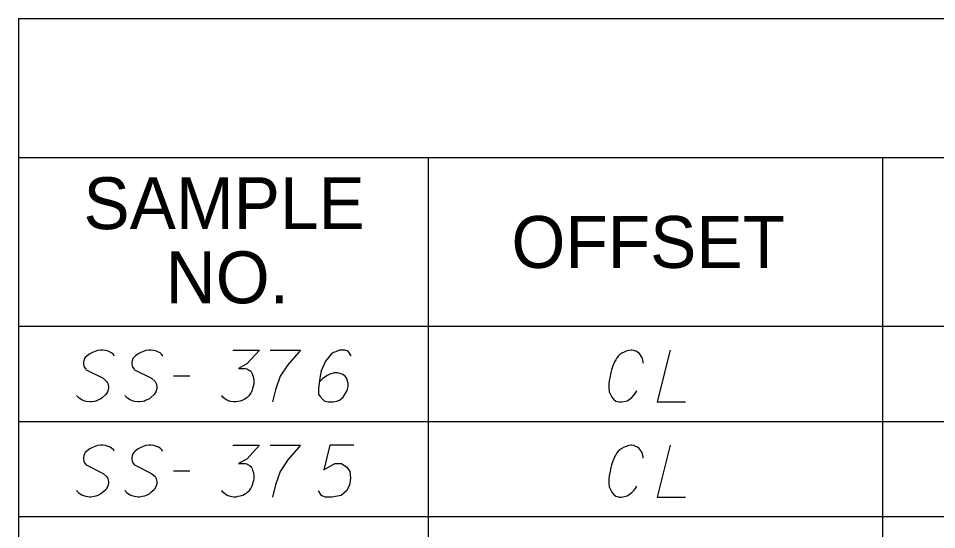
# Model space of a CAD drawing. Extents: x 2074207 to 2076812, y 516372 to 523312.
# Drawn here: x 2076260.6 to 2076345.6, y 517239.3 to 517286.6 of the extents above; entities that cross this region are included whole.
import ezdxf

# ---------------------------------------------------------------- set-up
doc = ezdxf.new("R2010")
doc.units = 0
for name, color, linetype in [('Prop DirtTable_ Soil Test Results - Outline (Major)', 7, 'Continuous'), ('Prop DirtTable_ Soil Test Results - Outline (Minor)', 7, 'Continuous'), ('Prop DirtTable_ Soil Test Results - Tx (Header - Small)', 7, 'Continuous'), ('Prop DirtTable_ Soil Test Results - Tx (Sample Data)', 7, 'Continuous')]:
    doc.layers.add(name, color=color, linetype=linetype)

msp = doc.modelspace()

# ---------------------------------------------------------------- linework, layer by layer
at = {"layer": 'Prop DirtTable_ Soil Test Results - Outline (Major)'}
for p, q in [((2076260.609, 517286.581), (2076260.609, 517258.096)), ((2076260.609, 517286.581), (2076811.903, 517286.581)), ((2076260.609, 517258.096), (2076260.609, 517249.296)), ((2076260.609, 517258.096), (2076811.903, 517258.096)), ((2076260.609, 517258.096), (2076811.903, 517258.096)), ((2076260.609, 517249.296), (2076260.609, 517240.496)), ((2076260.609, 517240.496), (2076260.609, 517231.696))]:
    msp.add_line(p, q, dxfattribs=at)
at = {"layer": 'Prop DirtTable_ Soil Test Results - Outline (Minor)'}
for p, q in [((2076260.609, 517273.696), (2076811.903, 517273.696)), ((2076298.545, 517273.696), (2076298.545, 517249.296)), ((2076340.594, 517273.696), (2076340.594, 517249.296)), ((2076260.609, 517249.296), (2076811.903, 517249.296)), ((2076260.609, 517249.296), (2076811.903, 517249.296)), ((2076298.546, 517249.296), (2076298.546, 517240.496)), ((2076340.594, 517249.296), (2076340.594, 517240.496)), ((2076260.609, 517240.496), (2076811.903, 517240.496)), ((2076260.609, 517240.496), (2076811.903, 517240.496)), ((2076298.546, 517240.496), (2076298.546, 517231.696)), ((2076340.594, 517240.496), (2076340.594, 517231.696))]:
    msp.add_line(p, q, dxfattribs=at)
at = {"layer": 'Prop DirtTable_ Soil Test Results - Tx (Sample Data)'}
for points in [[(2076269.488, 517255.331), (2076269.417, 517255.482), (2076269.241, 517255.633), (2076269.1, 517255.709), (2076268.923, 517255.785), (2076268.677, 517255.86), (2076268.394, 517255.898), (2076268.218, 517255.898), (2076267.936, 517255.86), (2076267.477, 517255.671), (2076267.23, 517255.558), (2076266.983, 517255.369), (2076266.807, 517255.218), (2076266.736, 517255.104), (2076266.666, 517254.915), (2076266.631, 517254.764), (2076266.631, 517254.613), (2076266.666, 517254.424), (2076266.736, 517254.273), (2076266.842, 517254.122), (2076266.878, 517254.084), (2076268.465, 517253.29), (2076268.782, 517252.988), (2076268.853, 517252.874), (2076268.888, 517252.799), (2076268.959, 517252.534), (2076268.959, 517252.383), (2076268.923, 517252.232), (2076268.853, 517252.043), (2076268.712, 517251.778), (2076268.359, 517251.476), (2076268.253, 517251.4), (2076267.971, 517251.249), (2076267.795, 517251.174), (2076267.618, 517251.136), (2076267.336, 517251.098), (2076267.23, 517251.098), (2076266.878, 517251.136), (2076266.666, 517251.211), (2076266.489, 517251.287), (2076266.243, 517251.438), (2076265.996, 517251.703)], [(2076273.968, 517255.331), (2076273.897, 517255.482), (2076273.721, 517255.633), (2076273.58, 517255.709), (2076273.403, 517255.785), (2076273.157, 517255.86), (2076272.874, 517255.898), (2076272.698, 517255.898), (2076272.416, 517255.86), (2076271.957, 517255.671), (2076271.71, 517255.558), (2076271.463, 517255.369), (2076271.287, 517255.218), (2076271.216, 517255.104), (2076271.146, 517254.915), (2076271.111, 517254.764), (2076271.111, 517254.613), (2076271.146, 517254.424), (2076271.216, 517254.273), (2076271.322, 517254.122), (2076271.358, 517254.084), (2076272.945, 517253.29), (2076273.262, 517252.988), (2076273.333, 517252.874), (2076273.368, 517252.799), (2076273.439, 517252.534), (2076273.439, 517252.383), (2076273.403, 517252.232), (2076273.333, 517252.043), (2076273.192, 517251.778), (2076272.839, 517251.476), (2076272.733, 517251.4), (2076272.451, 517251.249), (2076272.275, 517251.174), (2076272.098, 517251.136), (2076271.816, 517251.098), (2076271.71, 517251.098), (2076271.358, 517251.136), (2076271.146, 517251.211), (2076270.969, 517251.287), (2076270.723, 517251.438), (2076270.476, 517251.703)], [(2076280.459, 517255.898), (2076282.928, 517255.898), (2076281.764, 517254.613), (2076280.988, 517254.197), (2076281.623, 517254.197), (2076281.764, 517254.159), (2076281.834, 517254.122), (2076281.905, 517254.084), (2076281.975, 517254.046), (2076282.117, 517253.933), (2076282.187, 517253.819), (2076282.258, 517253.706), (2076282.293, 517253.592), (2076282.363, 517253.328), (2076282.399, 517253.101), (2076282.399, 517252.988), (2076282.399, 517252.837), (2076282.363, 517252.61), (2076282.328, 517252.459), (2076282.293, 517252.307), (2076282.258, 517252.194), (2076282.222, 517252.118), (2076282.187, 517252.043), (2076282.152, 517251.967), (2076282.081, 517251.854), (2076281.975, 517251.703), (2076281.87, 517251.589), (2076281.799, 517251.514), (2076281.693, 517251.438), (2076281.587, 517251.363), (2076281.446, 517251.287), (2076281.376, 517251.249), (2076281.129, 517251.174), (2076280.917, 517251.136), (2076280.776, 517251.098), (2076280.529, 517251.098), (2076280.247, 517251.136), (2076280.141, 517251.174), (2076280.035, 517251.211), (2076279.929, 517251.249), (2076279.824, 517251.325), (2076279.718, 517251.4), (2076279.541, 517251.552), (2076279.436, 517251.703)], [(2076283.916, 517255.898), (2076286.738, 517255.898), (2076286.561, 517255.709), (2076285.538, 517254.537), (2076284.833, 517253.479), (2076284.409, 517252.232), (2076284.127, 517251.098)], [(2076291.429, 517255.369), (2076291.147, 517255.785), (2076290.83, 517255.898), (2076290.336, 517255.898), (2076289.983, 517255.747), (2076289.771, 517255.671), (2076289.595, 517255.558), (2076289.031, 517254.878), (2076288.643, 517253.97), (2076288.537, 517253.479), (2076288.396, 517252.383), (2076288.396, 517251.816), (2076288.537, 517251.589), (2076288.819, 517251.287), (2076288.925, 517251.211), (2076289.278, 517251.098), (2076289.736, 517251.098), (2076290.089, 517251.174), (2076290.336, 517251.249), (2076290.689, 517251.552), (2076291.041, 517252.156), (2076291.147, 517252.534), (2076291.147, 517252.837), (2076290.971, 517253.328), (2076290.83, 517253.517), (2076290.583, 517253.668), (2076290.159, 517253.781), (2076289.842, 517253.781), (2076289.454, 517253.668), (2076289.207, 517253.555), (2076288.784, 517253.252), (2076288.572, 517253.063), (2076288.466, 517252.95)], [(2076318.45, 517254.689), (2076318.45, 517254.802), (2076318.415, 517254.953), (2076318.38, 517255.104), (2076318.309, 517255.255), (2076318.274, 517255.331), (2076318.168, 517255.482), (2076318.062, 517255.596), (2076317.921, 517255.709), (2076317.78, 517255.785), (2076317.569, 517255.86), (2076317.392, 517255.898), (2076317.322, 517255.898), (2076317.11, 517255.86), (2076316.863, 517255.785), (2076316.687, 517255.709), (2076316.475, 517255.596), (2076316.299, 517255.482), (2076316.122, 517255.331), (2076316.016, 517255.18), (2076315.911, 517254.991), (2076315.805, 517254.802), (2076315.628, 517254.424), (2076315.523, 517254.084), (2076315.452, 517253.819), (2076315.417, 517253.668), (2076315.381, 517253.479), (2076315.311, 517253.063), (2076315.276, 517252.761), (2076315.276, 517252.421), (2076315.311, 517252.043), (2076315.381, 517251.854), (2076315.487, 517251.665), (2076315.558, 517251.552), (2076315.699, 517251.363), (2076315.911, 517251.174), (2076316.052, 517251.136), (2076316.263, 517251.098), (2076316.404, 517251.098), (2076316.44, 517251.098), (2076316.687, 517251.136), (2076316.969, 517251.211), (2076317.145, 517251.325), (2076317.392, 517251.514), (2076317.604, 517251.741), (2076317.78, 517251.967), (2076317.851, 517252.118)], [(2076320.955, 517255.898), (2076319.756, 517251.098), (2076322.366, 517251.098)], [(2076274.956, 517253.517), (2076276.472, 517253.517)], [(2076269.488, 517246.531), (2076269.417, 517246.682), (2076269.241, 517246.833), (2076269.1, 517246.909), (2076268.923, 517246.985), (2076268.677, 517247.06), (2076268.394, 517247.098), (2076268.218, 517247.098), (2076267.936, 517247.06), (2076267.477, 517246.871), (2076267.23, 517246.758), (2076266.983, 517246.569), (2076266.807, 517246.418), (2076266.736, 517246.304), (2076266.666, 517246.115), (2076266.631, 517245.964), (2076266.631, 517245.813), (2076266.666, 517245.624), (2076266.736, 517245.473), (2076266.842, 517245.322), (2076266.878, 517245.284), (2076268.465, 517244.49), (2076268.782, 517244.188), (2076268.853, 517244.074), (2076268.888, 517243.999), (2076268.959, 517243.734), (2076268.959, 517243.583), (2076268.923, 517243.432), (2076268.853, 517243.243), (2076268.712, 517242.978), (2076268.359, 517242.676), (2076268.253, 517242.6), (2076267.971, 517242.449), (2076267.795, 517242.374), (2076267.618, 517242.336), (2076267.336, 517242.298), (2076267.23, 517242.298), (2076266.878, 517242.336), (2076266.666, 517242.411), (2076266.489, 517242.487), (2076266.243, 517242.638), (2076265.996, 517242.903)], [(2076273.968, 517246.531), (2076273.897, 517246.682), (2076273.721, 517246.833), (2076273.58, 517246.909), (2076273.403, 517246.985), (2076273.157, 517247.06), (2076272.874, 517247.098), (2076272.698, 517247.098), (2076272.416, 517247.06), (2076271.957, 517246.871), (2076271.71, 517246.758), (2076271.463, 517246.569), (2076271.287, 517246.418), (2076271.216, 517246.304), (2076271.146, 517246.115), (2076271.111, 517245.964), (2076271.111, 517245.813), (2076271.146, 517245.624), (2076271.216, 517245.473), (2076271.322, 517245.322), (2076271.358, 517245.284), (2076272.945, 517244.49), (2076273.262, 517244.188), (2076273.333, 517244.074), (2076273.368, 517243.999), (2076273.439, 517243.734), (2076273.439, 517243.583), (2076273.403, 517243.432), (2076273.333, 517243.243), (2076273.192, 517242.978), (2076272.839, 517242.676), (2076272.733, 517242.6), (2076272.451, 517242.449), (2076272.275, 517242.374), (2076272.098, 517242.336), (2076271.816, 517242.298), (2076271.71, 517242.298), (2076271.358, 517242.336), (2076271.146, 517242.411), (2076270.969, 517242.487), (2076270.723, 517242.638), (2076270.476, 517242.903)], [(2076280.459, 517247.098), (2076282.928, 517247.098), (2076281.764, 517245.813), (2076280.988, 517245.397), (2076281.623, 517245.397), (2076281.764, 517245.359), (2076281.834, 517245.322), (2076281.905, 517245.284), (2076281.975, 517245.246), (2076282.117, 517245.133), (2076282.187, 517245.019), (2076282.258, 517244.906), (2076282.293, 517244.792), (2076282.363, 517244.528), (2076282.399, 517244.301), (2076282.399, 517244.188), (2076282.399, 517244.037), (2076282.363, 517243.81), (2076282.328, 517243.659), (2076282.293, 517243.507), (2076282.258, 517243.394), (2076282.222, 517243.318), (2076282.187, 517243.243), (2076282.152, 517243.167), (2076282.081, 517243.054), (2076281.975, 517242.903), (2076281.87, 517242.789), (2076281.799, 517242.714), (2076281.693, 517242.638), (2076281.587, 517242.563), (2076281.446, 517242.487), (2076281.376, 517242.449), (2076281.129, 517242.374), (2076280.917, 517242.336), (2076280.776, 517242.298), (2076280.529, 517242.298), (2076280.247, 517242.336), (2076280.141, 517242.374), (2076280.035, 517242.411), (2076279.929, 517242.449), (2076279.824, 517242.525), (2076279.718, 517242.6), (2076279.541, 517242.752), (2076279.436, 517242.903)], [(2076283.916, 517247.098), (2076286.738, 517247.098), (2076286.561, 517246.909), (2076285.538, 517245.737), (2076284.833, 517244.679), (2076284.409, 517243.432), (2076284.127, 517242.298)], [(2076291.676, 517247.098), (2076289.454, 517247.098), (2076288.889, 517244.83), (2076289.912, 517245.397), (2076290.512, 517245.397), (2076291.006, 517245.057), (2076291.288, 517244.679), (2076291.359, 517244.037), (2076291.253, 517243.394), (2076290.971, 517242.865), (2076290.477, 517242.449), (2076289.63, 517242.298), (2076288.995, 517242.298), (2076288.678, 517242.449), (2076288.396, 517242.865)], [(2076318.45, 517245.889), (2076318.45, 517246.002), (2076318.415, 517246.153), (2076318.38, 517246.304), (2076318.309, 517246.455), (2076318.274, 517246.531), (2076318.168, 517246.682), (2076318.062, 517246.796), (2076317.921, 517246.909), (2076317.78, 517246.985), (2076317.569, 517247.06), (2076317.392, 517247.098), (2076317.322, 517247.098), (2076317.11, 517247.06), (2076316.863, 517246.985), (2076316.687, 517246.909), (2076316.475, 517246.796), (2076316.299, 517246.682), (2076316.122, 517246.531), (2076316.016, 517246.38), (2076315.911, 517246.191), (2076315.805, 517246.002), (2076315.628, 517245.624), (2076315.523, 517245.284), (2076315.452, 517245.019), (2076315.417, 517244.868), (2076315.381, 517244.679), (2076315.311, 517244.263), (2076315.276, 517243.961), (2076315.276, 517243.621), (2076315.311, 517243.243), (2076315.381, 517243.054), (2076315.487, 517242.865), (2076315.558, 517242.752), (2076315.699, 517242.563), (2076315.911, 517242.374), (2076316.052, 517242.336), (2076316.263, 517242.298), (2076316.404, 517242.298), (2076316.44, 517242.298), (2076316.687, 517242.336), (2076316.969, 517242.411), (2076317.145, 517242.525), (2076317.392, 517242.714), (2076317.604, 517242.941), (2076317.78, 517243.167), (2076317.851, 517243.318)], [(2076320.955, 517247.098), (2076319.756, 517242.298), (2076322.366, 517242.298)], [(2076274.956, 517244.717), (2076276.472, 517244.717)]]:
    msp.add_lwpolyline(points, dxfattribs=at)

# ---------------------------------------------------------------- texts
at = {"layer": 'Prop DirtTable_ Soil Test Results - Tx (Header - Small)'}
for s, p in [('SAMPLE', (2076266.632, 517267.082)), ('OFFSET', (2076306.254, 517263.496)), ('NO.', (2076274.244, 517260.225))]:
    msp.add_text(s, height=4.8, dxfattribs=at).set_placement(p)

doc.saveas('drawing.dxf')
